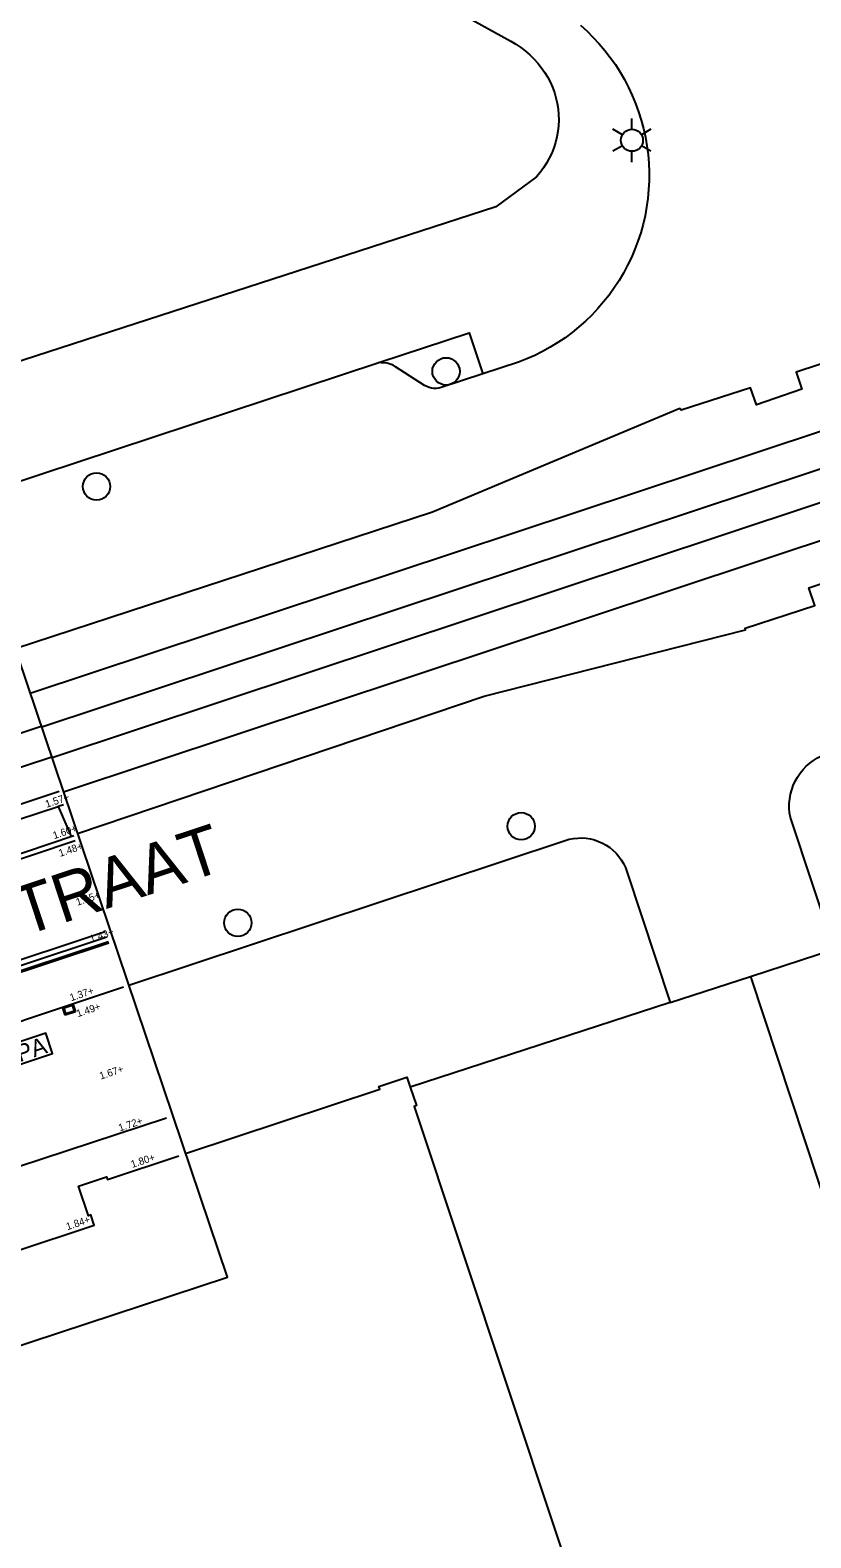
# Model space of a CAD drawing. Extents: x 122462 to 123306, y 485548 to 486417.
# Drawn here: x 122892.8 to 122924.9, y 486173.1 to 486235 of the extents above; entities that cross this region are included whole.
import ezdxf

# ---------------------------------------------------------------- set-up
doc = ezdxf.new("R2010")
doc.units = 0
for name, color, linetype in [('B-WE-AL-WERKGRENS-G', 7, 'Continuous'), ('B-WE-IE-MEUBILAIR_WEGMEUBILAIR_PARKEERAUTOMAAT-S', 7, 'Continuous'), ('B-WE-OG-HOOGTEPUNT-S', 7, 'Continuous'), ('B-WE-OG-TOPOGRAFIE_RAILS-G', 7, 'Continuous'), ('B-WE-OG-TOPOKAART-G', 7, 'Continuous'), ('B-WE-RI-HWA_KOLK-S', 7, 'Continuous'), ('B-WE-VH-MATERIAALGRENS-G', 7, 'Continuous'), ('B-WE-VH-MATERIAALGRENS_ASFALT-G', 7, 'Continuous'), ('B-WE-VW-MARKERING_LANGS_STREEP_11_010-G', 7, 'Continuous'), ('B-WE-VW-MARKERING_LANGS_STREEP_DOORGETROKKEN_010-G', 7, 'Continuous'), ('Level 1', 7, 'Continuous'), ('Level 17', 7, 'Continuous'), ('Level 37', 7, 'Continuous'), ('Level 50', 7, 'Continuous'), ('Level 53', 7, 'Continuous'), ('N werkgrens', 7, 'Continuous'), ('N-WE-GR-BOOM_DOORWORTELBARE RUIMTE-G', 7, 'Continuous'), ('V-WE-GR-BOOM-S', 7, 'Continuous')]:
    doc.layers.add(name, color=color, linetype=linetype)

msp = doc.modelspace()

# ---------------------------------------------------------------- linework, layer by layer
at = {"layer": 'B-WE-AL-WERKGRENS-G'}
msp.add_lwpolyline([(122857.632, 486078.279), (122830.484, 486160.606), (122900.937, 486183.81), (122887.855, 486222.555), (122665.445, 486149.273), (122678.196, 486110.449), (122807.072, 486152.895), (122835.324, 486068.154)], dxfattribs=at)
at = {"layer": 'B-WE-IE-MEUBILAIR_WEGMEUBILAIR_PARKEERAUTOMAAT-S'}
msp.add_lwpolyline([(122892.245, 486192.478), (122893.763, 486192.985), (122893.485, 486193.816), (122891.967, 486193.309)], close=True, dxfattribs=at)
at = {"layer": 'B-WE-OG-TOPOGRAFIE_RAILS-G'}
for p, q in [((122860.011, 486195.354), (122893.302, 486206.423)), ((122860.43, 486194.095), (122893.727, 486205.164)), ((122860.885, 486192.728), (122894.034, 486203.749))]:
    msp.add_line(p, q, dxfattribs=at)
at = {"layer": 'B-WE-OG-TOPOKAART-G'}
msp.add_lwpolyline([(122840.381, 486167.723), (122860.049, 486174.179), (122859.874, 486174.711), (122859.759, 486174.672), (122859.374, 486175.84), (122860.529, 486176.219), (122860.571, 486176.098), (122874.297, 486180.628), (122874.263, 486180.732), (122875.38, 486181.1), (122875.749, 486179.949), (122875.668, 486179.923), (122875.833, 486179.427), (122895.472, 486185.94), (122895.332, 486186.362), (122895.237, 486186.33), (122894.83, 486187.549), (122895.979, 486187.929), (122896.017, 486187.821), (122898.944, 486188.789)], dxfattribs=at)
at = {"layer": 'B-WE-RI-HWA_KOLK-S'}
for p, q in [((122894.171, 486194.888), (122894.598, 486195.03)), ((122894.282, 486194.556), (122894.171, 486194.888)), ((122894.218, 486194.904), (122894.22, 486194.899)), ((122894.232, 486194.893), (122894.277, 486194.908)), ((122894.277, 486194.908), (122894.308, 486194.918)), ((122894.708, 486194.698), (122894.282, 486194.556)), ((122894.313, 486194.936), (122894.315, 486194.931)), ((122894.337, 486194.943), (122894.338, 486194.939)), ((122894.351, 486194.932), (122894.427, 486194.958)), ((122894.432, 486194.975), (122894.433, 486194.97)), ((122894.455, 486194.983), (122894.457, 486194.978)), ((122894.47, 486194.972), (122894.545, 486194.997)), ((122894.55, 486195.015), (122894.552, 486195.01)), ((122894.598, 486195.03), (122894.708, 486194.698))]:
    msp.add_line(p, q, dxfattribs=at)
msp.add_lwpolyline([(122894.645, 486194.73), (122894.313, 486194.619), (122894.234, 486194.856), (122894.566, 486194.967)], close=True, dxfattribs=at)
for centre, start, end in [((122894.229, 486194.902), 198.4553, 288.4553), ((122894.305, 486194.928), 288.4553, 18.4553), ((122894.348, 486194.942), 198.4553, 288.4553), ((122894.424, 486194.967), 288.4553, 18.4553), ((122894.466, 486194.981), 198.4553, 288.4553), ((122894.542, 486195.007), 288.4553, 18.4553)]:
    msp.add_arc(centre, 0.01, start, end, dxfattribs=at)
at = {"layer": 'B-WE-VH-MATERIAALGRENS-G'}
msp.add_lwpolyline([(122826.354, 486164.961), (122825.848, 486166.443), (122832.41, 486168.591), (122840.754, 486171.332), (122848.12, 486173.75), (122858.853, 486177.307), (122858.545, 486178.241), (122874.617, 486183.538), (122874.928, 486182.584), (122877.008, 486183.297), (122898.435, 486190.341)], dxfattribs=at)
at = {"layer": 'B-WE-VH-MATERIAALGRENS_ASFALT-G'}
for points in [[(122894.213, 486203.196), (122893.995, 486203.123)], [(122896.06, 486197.572), (122886.118, 486194.28)]]:
    msp.add_lwpolyline(points, dxfattribs=at)
at = {"layer": 'B-WE-VW-MARKERING_LANGS_STREEP_11_010-G'}
for points in [[(122839.36, 486179.231), (122840.669, 486179.661), (122846.431, 486181.557), (122895.922, 486197.991)], [(122839.44, 486178.989), (122840.761, 486179.422), (122846.49, 486181.35), (122895.994, 486197.774)]]:
    msp.add_lwpolyline(points, dxfattribs=at)
at = {"layer": 'B-WE-VW-MARKERING_LANGS_STREEP_DOORGETROKKEN_010-G'}
msp.add_line((122896.079, 486197.515), (122886.189, 486194.24), dxfattribs=at)
msp.add_lwpolyline([(122838.137, 486182.943), (122845.99, 486185.533), (122855.924, 486188.815), (122864.876, 486191.785), (122870.826, 486193.778), (122879.74, 486196.789), (122887.719, 486199.383), (122894.693, 486201.733)], dxfattribs=at)
at = {"layer": 'Level 1'}
for points in [[(122899.224, 486188.882), (122907.197, 486191.52), (122907.16, 486191.63), (122908.309, 486192.009), (122908.447, 486191.601)], [(122908.447, 486191.601), (122908.698, 486190.847), (122908.604, 486190.816), (122924.101, 486144.211)]]:
    msp.add_lwpolyline(points, dxfattribs=at)
at = {"layer": 'Level 17'}
for p, q in [((122922.404, 486196.15), (122925.846, 486197.271)), ((122919.118, 486195.078), (122922.404, 486196.15)), ((122919.118, 486195.078), (122908.447, 486191.601))]:
    msp.add_line(p, q, dxfattribs=at)
for points in [[(123014.467, 486250), (123003.565, 486246.309), (122947.088, 486227.723), (122943.532, 486226.541), (122932.853, 486223.853), (122932.858, 486223.785), (122930.001, 486222.819), (122930.225, 486222.122), (122928.351, 486221.49), (122928.117, 486222.199), (122924.288, 486220.943), (122924.521, 486220.251), (122922.659, 486219.604), (122922.404, 486220.306), (122919.562, 486219.39), (122919.51, 486219.456), (122909.362, 486215.201), (122892.23, 486209.597)], [(122889.372, 486247.334), (122912.578, 486234.533), (122912.782, 486234.41), (122912.979, 486234.275), (122913.167, 486234.128), (122913.346, 486233.971), (122913.516, 486233.803), (122913.675, 486233.626), (122913.821, 486233.446), (122913.955, 486233.258), (122914.077, 486233.06), (122914.184, 486232.855), (122914.279, 486232.644), (122914.359, 486232.426), (122914.424, 486232.204), (122914.475, 486231.978), (122914.511, 486231.749), (122914.531, 486231.519), (122914.536, 486231.287), (122914.526, 486231.056), (122914.501, 486230.826), (122914.46, 486230.598), (122914.405, 486230.373), (122914.335, 486230.152), (122914.25, 486229.936), (122914.152, 486229.727), (122914.039, 486229.524), (122913.914, 486229.33), (122913.776, 486229.144), (122913.626, 486228.967), (122911.961, 486227.731), (122889.502, 486220.46)], [(122894.791, 486202.013), (122911.483, 486207.655), (122922.203, 486210.371), (122922.193, 486210.437), (122925.049, 486211.37), (122924.798, 486212.089), (122926.684, 486212.727), (122926.905, 486212.012), (122930.736, 486213.272), (122930.502, 486213.981), (122932.379, 486214.616), (122932.609, 486213.93), (122935.491, 486214.831), (122935.539, 486214.764), (122944.664, 486218.635), (122949.377, 486220.199), (123005.976, 486239.05), (123026.443, 486245.791)], [(122915.432, 486235.181), (122915.699, 486234.939), (122915.956, 486234.685), (122916.2, 486234.421), (122916.433, 486234.146), (122916.654, 486233.86), (122916.862, 486233.566), (122917.056, 486233.262), (122917.237, 486232.951), (122917.404, 486232.631), (122917.556, 486232.305), (122917.695, 486231.972), (122917.818, 486231.633), (122917.926, 486231.289), (122918.019, 486230.941), (122918.096, 486230.589), (122918.157, 486230.233), (122918.203, 486229.876), (122918.233, 486229.517), (122918.247, 486229.156), (122918.246, 486228.796), (122918.228, 486228.436), (122918.194, 486228.077), (122918.145, 486227.72), (122918.079, 486227.366), (122917.998, 486227.014), (122917.902, 486226.667), (122917.791, 486226.324), (122917.664, 486225.987), (122917.523, 486225.655), (122917.367, 486225.33), (122917.196, 486225.012), (122917.012, 486224.702), (122916.815, 486224.401), (122916.604, 486224.109), (122916.381, 486223.826), (122916.145, 486223.553), (122915.897, 486223.291), (122915.638, 486223.04), (122915.369, 486222.801), (122915.089, 486222.574), (122914.799, 486222.36), (122914.5, 486222.158), (122914.192, 486221.971), (122913.877, 486221.796), (122913.554, 486221.636), (122913.224, 486221.491), (122912.888, 486221.36), (122911.419, 486220.873)], [(122907.156, 486221.336), (122910.865, 486222.557), (122911.419, 486220.873)], [(122890.159, 486215.732), (122907.156, 486221.336)], [(122911.419, 486220.873), (122909.716, 486220.312), (122909.617, 486220.286), (122909.516, 486220.273), (122909.414, 486220.273), (122909.313, 486220.287), (122909.214, 486220.313), (122909.12, 486220.351), (122909.031, 486220.401), (122907.845, 486221.17), (122907.736, 486221.231), (122907.62, 486221.278), (122907.5, 486221.311), (122907.376, 486221.328), (122907.251, 486221.329), (122907.156, 486221.336)], [(122925.846, 486197.271), (122924.045, 486202.676), (122924.015, 486202.865), (122924, 486203.055), (122924.002, 486203.246), (122924.02, 486203.436), (122924.053, 486203.624), (122924.102, 486203.809), (122924.166, 486203.989), (122924.245, 486204.163), (122924.338, 486204.33), (122924.445, 486204.488), (122924.564, 486204.637), (122924.696, 486204.776), (122924.838, 486204.903), (122924.991, 486205.017), (122925.153, 486205.119), (122925.323, 486205.207), (122925.499, 486205.28), (122926.226, 486205.523)], [(122896.893, 486195.788), (122914.803, 486201.731), (122914.971, 486201.779), (122915.143, 486201.812), (122915.317, 486201.83), (122915.492, 486201.832), (122915.666, 486201.82), (122915.839, 486201.792), (122916.008, 486201.749), (122916.173, 486201.692), (122916.333, 486201.62), (122916.485, 486201.535), (122916.63, 486201.436), (122916.765, 486201.326), (122916.891, 486201.204), (122917.005, 486201.071), (122917.107, 486200.929), (122917.196, 486200.779), (122917.272, 486200.622), (122917.334, 486200.458), (122919.118, 486195.078)]]:
    msp.add_lwpolyline(points, dxfattribs=at)
at = {"layer": 'Level 37'}
for points in [[(122892.845, 486207.775), (123020.203, 486250)], [(123024.903, 486250), (122893.319, 486206.373)], [(123028.903, 486250), (122893.744, 486205.113)], [(123033.6, 486250), (122894.218, 486203.71)]]:
    msp.add_lwpolyline(points, dxfattribs=at)
at = {"layer": 'Level 50'}
for p, q in [((122917.543, 486230.911), (122917.543, 486231.361)), ((122917.153, 486230.686), (122916.763, 486230.911)), ((122918.322, 486230.911), (122917.932, 486230.686)), ((122917.153, 486230.236), (122916.763, 486230.011)), ((122917.543, 486229.561), (122917.543, 486230.011)), ((122918.322, 486230.011), (122917.932, 486230.236))]:
    msp.add_line(p, q, dxfattribs=at)
msp.add_circle((122917.543, 486230.461), 0.45, dxfattribs=at)
at = {"layer": 'Level 53'}
for centre in [(122909.912, 486220.979), (122895.571, 486216.252), (122913.001, 486202.311), (122901.367, 486198.346)]:
    msp.add_circle(centre, 0.56, dxfattribs=at)
at = {"layer": 'N werkgrens'}
msp.add_line((122922.404, 486196.15), (122939.611, 486144.046), dxfattribs=at)
at = {"layer": 'V-WE-GR-BOOM-S'}
for points in [[(122880.609, 486198.758), (122886.679, 486200.726), (122893.995, 486203.123)], [(122893.995, 486203.123), (122894.531, 486201.887)], [(122894.631, 486201.921), (122888.749, 486199.93), (122884.953, 486198.651), (122881.131, 486197.395), (122880.64, 486197.231)], [(122839.691, 486178.909), (122846.863, 486181.327), (122849.228, 486180.024), (122856.625, 486182.465), (122857.804, 486184.885), (122859.51, 486185.437), (122861.847, 486184.213), (122870.925, 486187.176), (122871.106, 486187.539), (122872.047, 486189.574), (122873.749, 486190.175), (122876.099, 486188.919), (122883.305, 486191.251), (122883.477, 486191.64), (122884.406, 486193.712), (122886.117, 486194.28), (122888.469, 486192.985), (122896.668, 486195.721)]]:
    msp.add_lwpolyline(points, dxfattribs=at)

# ---------------------------------------------------------------- texts
at = {"layer": 'B-WE-IE-MEUBILAIR_WEGMEUBILAIR_PARKEERAUTOMAAT-S'}
msp.add_text('PA', height=0.7, rotation=18.4553, dxfattribs=at).set_placement((122892.412, 486192.627))
at = {"layer": 'B-WE-OG-HOOGTEPUNT-S'}
for s, rotation, p in [('1.57+', 18.5998, (122893.522, 486203.068)), ('1.60+', 18.5998, (122893.832, 486201.782)), ('1.48+', 18.5998, (122894.072, 486201.054)), ('1.45+', 18.5998, (122894.782, 486199.045)), ('1.43+', 18.5998, (122895.344, 486197.536)), ('1.37+', 18.3542, (122894.523, 486195.127)), ('1.49+', 18.3542, (122894.801, 486194.476)), ('1.67+', 18.3542, (122895.742, 486191.914)), ('1.72+', 18.3542, (122896.525, 486189.783)), ('1.80+', 18.3542, (122897.033, 486188.289)), ('1.84+', 18.3542, (122894.373, 486185.734))]:
    msp.add_text(s, height=0.3, rotation=rotation, dxfattribs=at).set_placement(p)
at = {"layer": 'N-WE-GR-BOOM_DOORWORTELBARE RUIMTE-G'}
msp.add_text('SARPHATISTRAAT', height=2, rotation=18.25739, dxfattribs=at).set_placement((122878.184, 486193.046))

doc.saveas('drawing.dxf')
